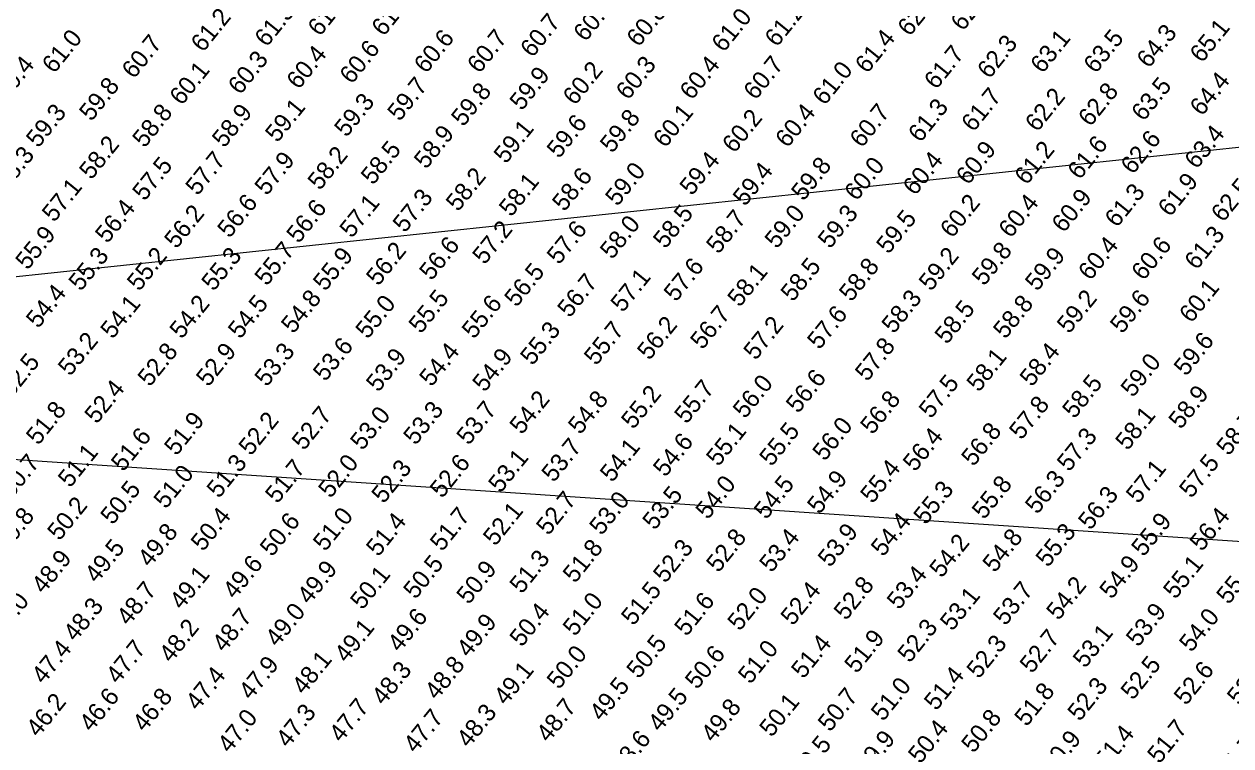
# Model space of a CAD drawing. Extents: x 401290 to 405690, y 1190598 to 1193998.
# Drawn here: x 403181 to 403862, y 1191808 to 1192215 of the extents above; entities that cross this region are included whole.
import ezdxf

# ---------------------------------------------------------------- set-up
doc = ezdxf.new("R2010")
doc.units = 0
for name, color, linetype in [('C-CHAN-POIT', 7, 'Continuous'), ('C-CHAN-WIDE', 7, 'Continuous'), ('V-TOPO-SOUN', 7, 'Continuous')]:
    doc.layers.add(name, color=color, linetype=linetype)

msp = doc.modelspace()

# ---------------------------------------------------------------- linework, layer by layer
at = {"layer": 'C-CHAN-POIT'}
msp.add_line((402579.39, 1192009.5), (404317.15, 1192193.7), dxfattribs=at)
at = {"layer": 'C-CHAN-WIDE'}
msp.add_line((402579.39, 1192009.5), (404790.92, 1191861.25), dxfattribs=at)

# ---------------------------------------------------------------- texts
at = {"layer": 'V-TOPO-SOUN'}
for s, p in [('61.5 ', (403348.17, 1192208.02)), ('61.4 ', (403384.2, 1192208.02)), ('62.5 ', (403711.2, 1192211.01)), ('61.3 ', (403318.19, 1192202.02)), ('60.7 ', (403498.17, 1192205.01)), ('60.8 ', (403528.19, 1192202.02)), ('61.2 ', (403606.18, 1192202.02)), ('62.1 ', (403681.18, 1192208.02)), ('61.2 ', (403282.2, 1192199.03)), ('60.7 ', (403468.19, 1192196.02)), ('61.0 ', (403576.19, 1192199.03)), ('60.7 ', (403438.2, 1192187.03)), ('63.5 ', (403786.2, 1192187.03)), ('64.3 ', (403816.18, 1192190.01)), ('65.1 ', (403846.17, 1192193.03)), ('61.0 ', (403198.17, 1192187.03)), ('60.7 ', (403243.19, 1192184.01)), ('60.6 ', (403366.18, 1192181.02)), ('60.6 ', (403408.18, 1192187.03)), ('61.4 ', (403657.19, 1192187.03)), ('62.3 ', (403726.19, 1192184.01)), ('63.1 ', (403756.18, 1192187.03)), ('60.3 ', (403303.19, 1192175.02)), ('60.4 ', (403336.2, 1192178)), ('61.7 ', (403696.17, 1192178)), ('60.4 ', (403171.17, 1192172.03)), ('60.1 ', (403270.19, 1192169.01)), ('60.2 ', (403492.2, 1192169.01)), ('60.3 ', (403522.19, 1192172.03)), ('60.4 ', (403558.18, 1192172.03)), ('60.7 ', (403594.2, 1192172.03)), ('61.0 ', (403633.18, 1192169.01)), ('59.7 ', (403393.19, 1192160.03)), ('59.9 ', (403462.18, 1192166.03)), ('63.5 ', (403813.2, 1192160.03)), ('64.4 ', (403846.17, 1192163.01)), ('59.8 ', (403219.17, 1192160.03)), ('59.8 ', (403429.18, 1192157.01)), ('61.7 ', (403717.2, 1192154.02)), ('62.2 ', (403753.19, 1192154.02)), ('62.8 ', (403783.18, 1192157.01)), ('59.1 ', (403324.19, 1192148.02)), ('59.3 ', (403363.2, 1192151.04)), ('61.3 ', (403687.18, 1192148.02)), ('59.3 ', (403189.18, 1192145.03)), ('58.8 ', (403249.19, 1192145.03)), ('58.9 ', (403294.17, 1192145.03)), ('59.8 ', (403513.2, 1192142.01)), ('60.1 ', (403543.19, 1192145.03)), ('60.2 ', (403582.19, 1192142.01)), ('60.4 ', (403612.18, 1192145.03)), ('60.7 ', (403654.18, 1192145.03)), ('59.1 ', (403453.19, 1192136.01)), ('59.6 ', (403483.18, 1192139.03)), ('63.4 ', (403843.19, 1192133.02)), ('58.2 ', (403219.17, 1192127.02)), ('58.9 ', (403408.18, 1192133.02)), ('61.6 ', (403777.17, 1192127.02)), ('62.6 ', (403807.19, 1192130.01)), ('58.3 ', (403171.17, 1192121.02)), ('58.2 ', (403348.17, 1192121.02)), ('58.5 ', (403378.19, 1192124.03)), ('60.9 ', (403714.18, 1192124.03)), ('61.2 ', (403747.19, 1192124.03)), ('57.5 ', (403249.19, 1192115.01)), ('57.7 ', (403279.18, 1192118.03)), ('57.9 ', (403318.19, 1192118.03)), ('59.4 ', (403558.18, 1192118.03)), ('59.8 ', (403621.17, 1192115.01)), ('60.0 ', (403651.19, 1192115.01)), ('60.4 ', (403684.2, 1192118.03)), ('58.2 ', (403426.19, 1192109.01)), ('58.6 ', (403486.2, 1192109.01)), ('59.0 ', (403516.18, 1192112.03)), ('59.4 ', (403588.2, 1192112.03)), ('61.9 ', (403828.19, 1192106.02)), ('57.1 ', (403198.17, 1192103)), ('58.1 ', (403456.18, 1192106.02)), ('61.3 ', (403798.17, 1192100.02)), ('62.5 ', (403858.18, 1192103)), ('56.6 ', (403297.19, 1192094.02)), ('57.1 ', (403366.18, 1192094.02)), ('57.3 ', (403396.17, 1192097.03)), ('60.2 ', (403705.19, 1192094.02)), ('60.4 ', (403738.2, 1192094.02)), ('60.9 ', (403768.19, 1192097.03)), ('56.4 ', (403228.19, 1192091.03)), ('56.2 ', (403267.2, 1192088.01)), ('56.6 ', (403336.2, 1192091.03)), ('58.5 ', (403543.19, 1192088.01)), ('58.7 ', (403573.17, 1192085.03)), ('59.0 ', (403606.18, 1192088.01)), ('59.3 ', (403636.2, 1192088.01)), ('59.5 ', (403669.2, 1192085.03)), ('57.2 ', (403441.18, 1192079.02)), ('57.6 ', (403483.18, 1192079.02)), ('58.0 ', (403513.2, 1192082.01)), ('55.9 ', (403183.18, 1192076.04)), ('61.3 ', (403843.19, 1192076.04)), ('55.7 ', (403318.19, 1192067.01)), ('56.2 ', (403381.18, 1192067.01)), ('56.6 ', (403411.2, 1192070.03)), ('59.8 ', (403723.17, 1192067.01)), ('60.4 ', (403783.18, 1192070.03)), ('60.6 ', (403813.2, 1192070.03)), ('55.3 ', (403213.2, 1192064.03)), ('55.2 ', (403246.17, 1192064.03)), ('55.3 ', (403288.2, 1192064.03)), ('55.9 ', (403351.19, 1192064.03)), ('57.6 ', (403549.19, 1192058.02)), ('58.5 ', (403615.2, 1192058.02)), ('59.2 ', (403693.19, 1192064.03)), ('59.9 ', (403753.19, 1192064.03)), ('56.5 ', (403459.2, 1192055.01)), ('58.1 ', (403585.18, 1192055.01)), ('58.8 ', (403648.17, 1192058.02)), ('56.7 ', (403489.18, 1192049.03)), ('57.1 ', (403519.2, 1192052.02)), ('60.1 ', (403840.2, 1192046.02)), ('54.4 ', (403189.18, 1192043.03)), ('54.8 ', (403333.18, 1192040.01)), ('55.5 ', (403405.19, 1192040.01)), ('58.3 ', (403672.19, 1192040.01)), ('59.2 ', (403771.17, 1192040.01)), ('59.6 ', (403801.19, 1192040.01)), ('54.1 ', (403231.18, 1192037.03)), ('54.2 ', (403270.19, 1192037.03)), ('54.5 ', (403303.19, 1192037.03)), ('55.0 ', (403375.17, 1192037.03)), ('55.6 ', (403435.18, 1192037.03)), ('56.7 ', (403564.18, 1192031.02)), ('57.6 ', (403630.19, 1192031.02)), ('58.5 ', (403702.17, 1192034.01)), ('58.8 ', (403735.18, 1192037.03)), ('56.2 ', (403534.2, 1192025.02)), ('57.2 ', (403594.2, 1192025.02)), ('55.3 ', (403468.19, 1192022.03)), ('55.7 ', (403504.18, 1192022.03)), ('53.2 ', (403207.2, 1192016.03)), ('53.6 ', (403351.19, 1192013.01)), ('57.8 ', (403657.19, 1192013.01)), ('59.6 ', (403837.18, 1192016.03)), ('52.5 ', (403174.19, 1192004.02)), ('52.8 ', (403252.18, 1192010.03)), ('52.9 ', (403285.18, 1192010.03)), ('53.3 ', (403318.19, 1192010.03)), ('53.9 ', (403381.18, 1192007.01)), ('54.4 ', (403411.2, 1192010.03)), ('54.9 ', (403441.18, 1192007.01)), ('58.1 ', (403720.19, 1192007.01)), ('58.4 ', (403750.17, 1192010.03)), ('59.0 ', (403807.19, 1192004.02)), ('55.7 ', (403555.19, 1191989.03)), ('56.0 ', (403588.2, 1191992.01)), ('56.6 ', (403618.19, 1191995.03)), ('57.5 ', (403693.19, 1191992.01)), ('58.5 ', (403774.19, 1191992.01)), ('52.4 ', (403222.19, 1191989.03)), ('55.2 ', (403525.17, 1191986.01)), ('58.9 ', (403834.2, 1191986.01)), ('51.8 ', (403189.18, 1191977.02)), ('53.3 ', (403402.18, 1191977.02)), ('53.7 ', (403432.2, 1191977.02)), ('54.2 ', (403462.18, 1191983.02)), ('54.8 ', (403495.19, 1191983.02)), ('56.8 ', (403660.18, 1191983.02)), ('57.8 ', (403744.2, 1191980.01)), ('51.9 ', (403267.2, 1191971.02)), ('52.2 ', (403309.2, 1191971.02)), ('52.7 ', (403339.18, 1191974.04)), ('53.0 ', (403372.19, 1191974.04)), ('58.1 ', (403804.18, 1191974.04)), ('58.7 ', (403861.2, 1191971.02)), ('55.1 ', (403573.17, 1191965.01)), ('55.5 ', (403603.19, 1191965.01)), ('56.0 ', (403633.18, 1191968.03)), ('56.8 ', (403717.2, 1191965.01)), ('51.6 ', (403237.18, 1191962.03)), ('53.7 ', (403480.19, 1191956.02)), ('54.6 ', (403543.19, 1191959.01)), ('56.4 ', (403684.2, 1191962.03)), ('57.3 ', (403771.17, 1191962.03)), ('51.1 ', (403207.2, 1191953)), ('53.1 ', (403450.17, 1191950.02)), ('54.1 ', (403513.2, 1191956.02)), ('50.7 ', (403174.19, 1191947.03)), ('51.3 ', (403291.18, 1191947.03)), ('51.7 ', (403324.19, 1191944.02)), ('52.0 ', (403354.18, 1191947.03)), ('52.3 ', (403384.2, 1191944.02)), ('52.6 ', (403417.2, 1191947.03)), ('55.4 ', (403660.18, 1191944.02)), ('57.1 ', (403810.18, 1191944.02)), ('57.5 ', (403840.2, 1191947.03)), ('51.0 ', (403261.2, 1191941.03)), ('54.5 ', (403600.17, 1191935.03)), ('54.9 ', (403630.19, 1191938.01)), ('56.3 ', (403753.19, 1191938.01)), ('50.5 ', (403231.18, 1191932.01)), ('53.5 ', (403537.18, 1191929.02)), ('54.0 ', (403567.2, 1191935.03)), ('55.3 ', (403690.2, 1191932.01)), ('55.8 ', (403723.17, 1191935.03)), ('56.3 ', (403783.18, 1191929.02)), ('50.2 ', (403201.19, 1191923.02)), ('52.7 ', (403477.18, 1191926.04)), ('53.0 ', (403507.2, 1191926.04)), ('49.8 ', (403171.17, 1191917.01)), ('50.4 ', (403282.2, 1191917.01)), ('51.0 ', (403351.19, 1191917.01)), ('51.7 ', (403417.2, 1191917.01)), ('52.1 ', (403447.19, 1191920.03)), ('56.4 ', (403846.17, 1191917.01)), ('50.6 ', (403321.17, 1191914.03)), ('51.4 ', (403381.18, 1191914.03)), ('54.4 ', (403666.18, 1191914.03)), ('55.9 ', (403813.2, 1191914.03)), ('49.8 ', (403252.18, 1191908.02)), ('52.8 ', (403573.17, 1191905.01)), ('53.4 ', (403603.19, 1191905.01)), ('53.9 ', (403636.2, 1191908.02)), ('54.2 ', (403699.19, 1191902.02)), ('54.8 ', (403729.18, 1191905.01)), ('55.3 ', (403759.2, 1191908.02)), ('49.5 ', (403222.19, 1191899.04)), ('51.8 ', (403492.2, 1191899.04)), ('52.3 ', (403543.19, 1191899.04)), ('48.9 ', (403192.2, 1191893.03)), ('49.6 ', (403300.17, 1191890.01)), ('50.5 ', (403402.18, 1191890.01)), ('51.3 ', (403462.18, 1191893.03)), ('54.9 ', (403795.19, 1191890.01)), ('55.1 ', (403831.18, 1191890.01)), ('49.1 ', (403270.19, 1191884.01)), ('49.9 ', (403342.2, 1191887.03)), ('50.1 ', (403372.19, 1191884.01)), ('50.9 ', (403432.2, 1191887.03)), ('53.4 ', (403675.17, 1191884.01)), ('55.4 ', (403861.2, 1191887.03)), ('48.7 ', (403240.2, 1191875.02)), ('51.5 ', (403525.17, 1191875.02)), ('52.4 ', (403615.2, 1191875.02)), ('52.8 ', (403645.19, 1191878.01)), ('53.7 ', (403735.18, 1191875.02)), ('54.2 ', (403765.2, 1191878.01)), ('48.0 ', (403168.19, 1191869.02)), ('51.0 ', (403492.2, 1191869.02)), ('51.6 ', (403555.19, 1191869.02)), ('52.0 ', (403585.18, 1191872.03)), ('53.1 ', (403705.19, 1191872.03)), ('48.3 ', (403210.18, 1191866.03)), ('48.7 ', (403294.17, 1191860.03)), ('49.0 ', (403324.19, 1191863.01)), ('49.6 ', (403393.19, 1191860.03)), ('50.4 ', (403462.18, 1191863.01)), ('53.9 ', (403810.18, 1191863.01)), ('48.2 ', (403264.18, 1191854.02)), ('49.9 ', (403432.2, 1191857.01)), ('52.3 ', (403681.18, 1191854.02)), ('54.0 ', (403840.2, 1191860.03)), ('49.1 ', (403363.2, 1191854.02)), ('51.9 ', (403651.19, 1191848.02)), ('52.7 ', (403750.17, 1191848.02)), ('53.1 ', (403780.19, 1191851.04)), ('47.4 ', (403192.2, 1191842.01)), ('47.7 ', (403234.2, 1191842.01)), ('50.5 ', (403528.19, 1191845.03)), ('51.0 ', (403591.18, 1191842.01)), ('51.4 ', (403621.17, 1191845.03)), ('52.3 ', (403720.19, 1191845.03)), ('48.1 ', (403339.18, 1191836.01)), ('50.0 ', (403483.18, 1191839.03)), ('50.6 ', (403561.2, 1191839.03)), ('52.5 ', (403807.19, 1191833.02)), ('47.4 ', (403279.18, 1191827.02)), ('47.9 ', (403309.2, 1191833.02)), ('48.3 ', (403384.2, 1191830.01)), ('48.8 ', (403414.18, 1191833.02)), ('49.1 ', (403453.19, 1191830.01)), ('51.4 ', (403696.17, 1191827.02)), ('52.6 ', (403837.18, 1191830.01)), ('52.8 ', (403867.2, 1191830.01)), ('49.5 ', (403507.2, 1191821.02)), ('51.0 ', (403666.18, 1191821.02)), ('52.3 ', (403777.17, 1191821.02)), ('46.6 ', (403219.17, 1191815.01)), ('46.8 ', (403249.19, 1191815.01)), ('49.5 ', (403540.2, 1191815.01)), ('50.7 ', (403636.2, 1191815.01)), ('51.8 ', (403747.19, 1191818.03)), ('46.2 ', (403189.18, 1191812.03)), ('47.3 ', (403330.19, 1191806.02)), ('47.7 ', (403360.18, 1191809.01)), ('48.3 ', (403432.2, 1191806.02)), ('48.7 ', (403477.18, 1191809.01)), ('49.8 ', (403570.19, 1191809.01)), ('50.1 ', (403603.19, 1191812.03)), ('47.0 ', (403297.19, 1191803.01)), ('47.7 ', (403402.18, 1191803.01)), ('50.8 ', (403717.2, 1191803.01)), ('50.4 ', (403687.18, 1191797.03)), ('51.4 ', (403792.2, 1191794.02)), ('51.7 ', (403822.19, 1191797.03)), ('48.6 ', (403519.2, 1191791.03)), ('49.5 ', (403621.17, 1191788.01)), ('49.9 ', (403657.19, 1191791.03)), ('50.9 ', (403762.18, 1191791.03)), ('51.7 ', (403861.2, 1191788.01))]:
    msp.add_text(s, height=9.996, rotation=51.05, dxfattribs=at).set_placement(p)

doc.saveas('drawing.dxf')
